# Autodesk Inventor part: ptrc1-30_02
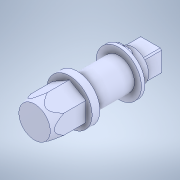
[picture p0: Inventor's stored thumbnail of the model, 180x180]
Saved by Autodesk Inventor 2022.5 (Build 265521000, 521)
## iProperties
Created: 2023-04
Part Number: ptrc1-30_02
Material: Generic
Document SubType Name: Modeling
Designer: ImaoCorp
Density: 1 g/cm^3
Appearance: Default
Author: ImaoCorp
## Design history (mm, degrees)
feature "ptrc1-30_02"
node "ソリッド1"
